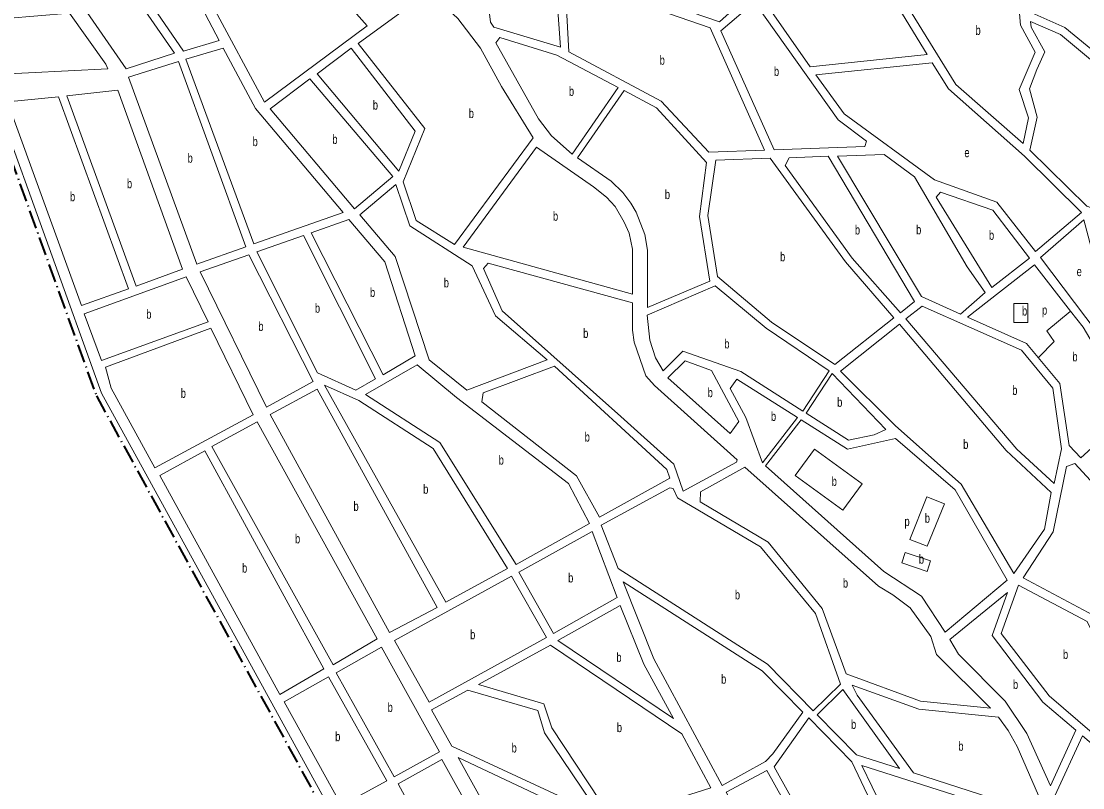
# Model space of a CAD drawing. Extents: x 639657 to 671642, y 222838 to 252123.
# Drawn here: x 652754 to 653901, y 228228 to 229056 of the extents above; entities that cross this region are included whole.
import ezdxf

# ---------------------------------------------------------------- set-up
doc = ezdxf.new("R2010")
doc.units = 0
doc.header["$LTSCALE"] = 4
doc.linetypes.add('DOT_DASHED', pattern=[7.7, 5, -1.2, 0.3, -1.2])
for name, color, linetype, lineweight in [('1', 7, 'Continuous', 13), ('21', 7, 'Continuous', 13), ('4', 7, 'DOT_DASHED', 40)]:
    doc.layers.add(name, color=color, linetype=linetype, lineweight=lineweight)
doc.layers.add('7', color=7, linetype='Continuous')

msp = doc.modelspace()

# ---------------------------------------------------------------- linework, layer by layer
at = {"layer": '1'}
for points in [[(653811.35, 229115.41), (653842.94, 229066.23), (653881.75, 229048.94), (653947.92, 228994.59), (653951.13, 229032.65), (653909.17, 229080.36), (653893.82, 229167.24), (653886.37, 229182.41), (653818.23, 229185.35), (653755.78, 229259.96), (653702.93, 229253.35), (653625.12, 229281.73), (653610.16, 229299.44), (653612.04, 229325.39), (653532.94, 229354.14), (653459.475, 229409.417), (653426.2, 229326.26), (653561.85, 229249.61), (653635.08, 229238.77), (653687.55, 229168.52), (653763.64, 229139.35)], [(652833.34, 229163.27), (652929.38, 229023.56), (652967.93, 229035.13), (652948.95, 229070.5), (652943.35, 229138.98), (652895.2, 229194.68)], [(653387.08, 229096.96), (653508.45, 229055.25), (653540.1, 229083.87), (653435.62, 229176.62), (653392.23, 229190.25)], [(652777.42, 229134.78), (652867.47, 229004.32), (652919.66, 229021.23), (652824.32, 229158.9)], [(653675.24, 229131.17), (653763.75, 228987.51), (653836.5, 228923.62), (653842.49, 228951.64), (653832.4, 228982.03), (653849.8, 229022.23), (653833.96, 229051.69), (653832.73, 229064), (653806.07, 229108.19), (653759.6, 229131.24), (653689.3, 229158.52)], [(653260.52, 229131.76), (653258.29, 229078.93), (653261.1, 229054.91), (653264.61, 229049.33), (653336.54, 229027.63), (653330.99, 229107.86)], [(653341.47, 229103.1), (653345.53, 229022.76), (653445.35, 228969.54), (653497.06, 228914.56), (653557.04, 228916.62), (653498.36, 229048.66)], [(653194.73, 229087.85), (653225.83, 229058.89), (653250.17, 229026.77), (653272.93, 228985.4), (653307.12, 228929.98), (653222.29, 228814.7), (653180.59, 228840.74), (653166.78, 228882.3), (653189.98, 228939.93), (653117.98, 229031.93)], [(653510.09, 229045.26), (653567.52, 228916.98), (653665.49, 228920.35), (653667.35, 228926.26), (653636.64, 228949.17), (653546.22, 229076.33)], [(652543.05, 229031.04), (652552.08, 228972.93), (652718.57, 228997.74), (652847.65, 229004.49), (652845.44, 229009.49), (652806.27, 229064.53), (652737.52, 229058.81)], [(653843.89, 228916.6), (653905.35, 228856.27), (653975.95, 228830.48), (653996.82, 228842.26), (653939.76, 228989.19), (653877.04, 229041.4), (653844.69, 229055.43), (653845.41, 229049.52), (653860.01, 229022.64), (653851.36, 229003.59), (653843.68, 228982.87), (653851.89, 228952.15)], [(653266.98, 229032.3), (653312.76, 228950.32), (653326.89, 228932.14), (653349.21, 228912.27), (653398.97, 228984.28), (653332.75, 229019.28), (653271.26, 229038.12)], [(652931.97, 229014.97), (653005.47, 228815.27), (653102, 228849.35), (653007.18, 228961.39), (652972.08, 229026.65)], [(653110.57, 229026.7), (653073.61, 228999.02), (653161.87, 228894.05), (653179.56, 228937.12)], [(652870.01, 228995.46), (652943.68, 228793.55), (652996.77, 228812.13), (652923.94, 229012.45)], [(653612.79, 228998.06), (653643.23, 228955.7), (653740.85, 228884.57), (653808.05, 228860.48), (653849.87, 228806.97), (653899.67, 228849.27), (653838.05, 228909.92), (653755.97, 228982.87), (653738.36, 229010.98)], [(653065.94, 228993.42), (653022.81, 228961.1), (653114.13, 228853.3), (653155.38, 228888.19)], [(652738.93, 228968.88), (652794.2, 228974.09), (652869.76, 228766.76), (652819.08, 228748.78)], [(652803.33, 228975.29), (652858.44, 228981.2), (652928.38, 228788.2), (652878.13, 228769.68)], [(653354.92, 228908.42), (653391.38, 228883), (653403.94, 228871), (653412.79, 228859.36), (653418.52, 228849.55), (653428, 228825.39), (653430.85, 228808.57), (653430.56, 228746.6), (653497.92, 228775.24), (653487.06, 228844.76), (653494.52, 228903.21), (653440.32, 228962.32), (653405.48, 228980.92)], [(653231.49, 228811.93), (653414.5, 228761.06), (653414.45, 228809.71), (653410.8, 228826.89), (653405.66, 228838.81), (653395.87, 228855.71), (653386.33, 228865.78), (653372.32, 228876.92), (653310.65, 228919.67)], [(653504.72, 228905.87), (653496.09, 228845.92), (653506.4, 228780.16), (653564.87, 228730.84), (653633, 228685.1), (653697.07, 228735.66), (653644.64, 228795.91), (653563.14, 228908.04)], [(653583.94, 228908.32), (653579.66, 228899.87), (653651.83, 228799.96), (653703.94, 228740.95), (653719.22, 228753.3), (653625.96, 228910.06)], [(653635.96, 228910.26), (653726.73, 228758.43), (653768.82, 228739.64), (653795.56, 228762.79), (653776.07, 228790.51), (653719.23, 228887.83), (653686.53, 228911.81)], [(653173.87, 228834.68), (653241.39, 228791.65), (653266.39, 228737.49), (653322.16, 228690.26), (653235.3, 228657.47), (653194.91, 228690.31), (653157.91, 228801.86), (653119.84, 228846.81), (653158.67, 228879.38)], [(653747.5, 228871.37), (653742.68, 228865.66), (653802.86, 228768.18), (653843.66, 228799.86), (653803.99, 228851.76)], [(653067.17, 228827.36), (653144.99, 228674.08), (653179.76, 228694.57), (653147.01, 228795.82), (653107.92, 228841.84)], [(653855.36, 228800.75), (653916.47, 228719.62), (653929.74, 228737.89), (653902.28, 228841.48)], [(653008.71, 228806.68), (653074.23, 228676.26), (653115.47, 228657.54), (653136.89, 228669.5), (653058.85, 228824.45)], [(652947.4, 228785.23), (653019.03, 228638.92), (653069.36, 228666.74), (652999.8, 228803.65)], [(652821.89, 228739.97), (652840.57, 228689.4), (652955.83, 228731.26), (652932.05, 228779.61)], [(653430.48, 228738.32), (653433.25, 228711.51), (653439.43, 228692.13), (653447.49, 228678.34), (653468.81, 228699.58), (653531.66, 228677.47), (653598.44, 228634.79), (653627.11, 228678.36), (653559.03, 228724.21), (653503.74, 228770.16)], [(653709.76, 228734.46), (653829.79, 228593.75), (653870.32, 228556.46), (653878.21, 228593.9), (653868.82, 228659.6), (653834.99, 228700.45), (653727.56, 228748.12)], [(652844.86, 228682.25), (652851.16, 228659.55), (652898.38, 228573.69), (653004.64, 228630.84), (652958.85, 228724.44)], [(653826.76, 228459.32), (653769.76, 228555.94), (653698.73, 228618.87), (653639.42, 228677.92), (653702.9, 228728.64), (653818.4, 228592.21), (653866.88, 228546.78), (653859.65, 228507.35)], [(653206.2, 228600.89), (653288.85, 228469.23), (653368.14, 228513.3), (653345.26, 228556.5), (653224.2, 228649.59), (653181.78, 228684.78), (653126.01, 228652.88)], [(653452.72, 228670.62), (653520.15, 228610.68), (653529.41, 228623.67), (653500, 228678.67), (653471.26, 228689)], [(653251.73, 228644.68), (653354.05, 228564.86), (653378.8, 228520.38), (653454.73, 228562.27), (653451.69, 228571.88), (653330.19, 228683.35), (653253.21, 228654.41)], [(653602.21, 228632.6), (653648.04, 228603.5), (653675.54, 228609.18), (653688.31, 228614.81), (653630.13, 228675.41)], [(653199, 228594.31), (653279.57, 228464.93), (653212.69, 228428.3), (653081.78, 228662.79), (653118.72, 228646.37)], [(653527.38, 228669.34), (653520, 228659.32), (653536.92, 228627.99), (653554.97, 228578.97), (653592.82, 228627.95)], [(653151.82, 228395.79), (653023.02, 228631.03), (653073.89, 228658.37), (653203.41, 228422.7)], [(653091.08, 228360.66), (652960.07, 228596.53), (653008.96, 228623.32), (653138.44, 228388.88)], [(653558.391, 228575.659), (653596.75, 228625.43), (653646.88, 228593.77), (653698.66, 228605.16), (653763.28, 228549.74), (653819.52, 228452.22), (653752.33, 228395.93), (653726.89, 228435.09), (653686.09, 228461.48)], [(652903.55, 228565.09), (652952.29, 228592), (653080.84, 228356.36), (653033.35, 228328.69)], [(653561.02, 228493.41), (653487.65, 228536.84), (653487.93, 228547.54), (653536.06, 228574.24), (653680.27, 228445.68), (653695.68, 228436.48), (653714.42, 228422.48), (653736.72, 228391.25), (653743.08, 228372), (653801.52, 228314.11), (653725.6, 228321.5), (653645.58, 228351), (653619.42, 228421.47)], [(653883.4, 228574.99), (653892.51, 228578.03), (653989.83, 228472.58), (654010.14, 228473.42), (654027.16, 228494.01), (654071.54, 228420.2), (653955.49, 228346.83), (653940.12, 228357.61), (653912.25, 228414.53), (653836.58, 228454.74), (653868.93, 228504.55)], [(653380.72, 228511.6), (653454.87, 228551.84), (653458.36, 228551.37), (653463.02, 228541.06), (653552.74, 228488.27), (653612.24, 228416.07), (653639.23, 228339.97), (653609.75, 228311.07), (653560.25, 228361.36), (653398.9, 228464.66)], [(653370.93, 228504.69), (653291.83, 228460.71), (653329.25, 228394.79), (653398.11, 228433.35)], [(653157.25, 228387.01), (653194.85, 228320.51), (653321.48, 228390.25), (653283.74, 228456.38)], [(653404.44, 228450.34), (653437.73, 228367.28), (653511.56, 228230.51), (653558.29, 228256.25), (653566.32, 228264.61), (653598.58, 228309.84), (653554.59, 228354.25)], [(653831.73, 228446.72), (653812.92, 228394.44), (653864.68, 228327.14), (653911.23, 228287.41), (653948.52, 228339.54), (653933.49, 228350.49), (653905.67, 228407.69)], [(653819.62, 228439.04), (653757.25, 228388.11), (653766.82, 228372.14), (653817.17, 228321.64), (653840.72, 228286.55), (653866.34, 228230.26), (653893.6, 228290.35), (653857.99, 228320.34), (653803.31, 228392.47)], [(653401.31, 228424.87), (653333.9, 228387.08), (653458.92, 228302.92), (653426.8, 228361.55)], [(653205.89, 228266.88), (653143.13, 228379.86), (653094.22, 228352.06), (653156.81, 228239.91)], [(653325.91, 228382.16), (653247.99, 228339.7), (653318.74, 228318.65), (653327.17, 228292.58), (653392.42, 228194.12), (653499.27, 228227.94), (653467.85, 228286.25)], [(653085.89, 228347.95), (653037.9, 228320.81), (653099.99, 228208.73), (653149.09, 228235.57)], [(653197.16, 228312.27), (653219.24, 228273), (653379.03, 228198.8), (653319.46, 228287.24), (653312.06, 228311.32), (653236.68, 228333.43)], [(653641.67, 228334.17), (653613.95, 228306.89), (653656.44, 228263.56), (653703, 228248.91)], [(653651.85, 228338.72), (653657.26, 228328.17), (653718.27, 228244.19), (653863.13, 228197.32), (653830.19, 228272.71), (653820.3, 228289.85), (653809.93, 228304.42), (653723.76, 228312.79)], [(653567.5, 228250.7), (653645.21, 228111.53), (653713.86, 228148.9), (653688.56, 228177.86), (653651.58, 228255.91), (653604.89, 228303.37)], [(653999.51, 228200.07), (653900.72, 228283.99), (653871.05, 228219.16), (653882.26, 228194.82), (653900.61, 228186.51), (653911.58, 228169.53), (653962.19, 228138.29), (654049.93, 228120.63), (654055.79, 228128.91)], [(653226.16, 228260.62), (653292.25, 228141.38), (653378.96, 228188.7)], [(653208.5, 228258.42), (653161.31, 228232.13), (653229.35, 228106.69), (653278.05, 228133.53)], [(653662.5, 228252.19), (653695.74, 228182.83), (653742.82, 228130.11), (653893.21, 228126.66), (653867.9, 228186.65)], [(653515.72, 228223.11), (653593.54, 228082.92), (653637.44, 228107.31), (653559.51, 228246.59)]]:
    msp.add_lwpolyline(points, close=True, dxfattribs=at)
for points in [[(653549.53, 229088.24), (653606.47, 229006.54), (653732.9, 229019.83), (653667.88, 229126.8), (653605.07, 229151.28), (653556.41, 229241.94), (653537.956, 229252.419)], [(652960.607, 229076.586), (652961.09, 229072.02), (653016.89, 228968.23), (653127.83, 229050.75), (653090.71, 229092.8), (653067.566, 229120.908)], [(652721.144, 228967.066), (652727.37, 228968.04), (652840.64, 228654.32), (653505.16, 227445.52), (653736.61, 227336.66), (653997.8, 227222.88), (654191.766, 227095.851), (654189.938, 227093.586), (654189.534, 227093.086)], [(653438.24, 228662.51), (653429.07, 228672.86), (653416.16, 228709.15), (653414.51, 228722.15), (653414.42, 228751.66), (653258.36, 228794.71), (653253.38, 228788.89)], [(653253.38, 228788.89), (653273.73, 228743.21), (653402.01, 228629.13)], [(653887.861, 228742.805), (653848.79, 228792.57), (653776.51, 228736.28)], [(653852.938, 228692.656), (653876.44, 228664.46), (653886.43, 228597.52), (653898.88, 228584.45), (653933.51, 228615.57), (653957.16, 228631.28), (653901.62, 228725.28), (653887.861, 228742.805)], [(653776.51, 228736.28), (653840.24, 228707.89), (653852.938, 228692.656)], [(653469.17, 228548.28), (653527.02, 228579.53), (653527.55, 228582), (653438.24, 228662.51)], [(653402.01, 228629.13), (653459.3, 228577.49), (653469.17, 228548.28)]]:
    msp.add_lwpolyline(points, dxfattribs=at)
at = {"layer": '21'}
for points in [[(653826.477, 228750.809), (653841.855, 228750.809), (653841.855, 228730.293), (653826.477, 228730.293)], [(653611.183, 228593.732), (653662.716, 228556.297), (653641.939, 228527.696), (653590.406, 228565.131)], [(653714.344, 228496.281), (653733.107, 228488.772), (653751.508, 228534.749), (653732.745, 228542.258)], [(653709.218, 228482.176), (653736.71, 228473.006), (653732.926, 228461.66), (653705.434, 228470.83)]]:
    msp.add_lwpolyline(points, close=True, dxfattribs=at)
msp.add_lwpolyline([(653852.938, 228692.656), (653853.438, 228693.156), (653870.048, 228709.777), (653862.359, 228721.317), (653887.361, 228742.384), (653887.861, 228742.805)], dxfattribs=at)
at = {"layer": '4'}
msp.add_lwpolyline([(652721.144, 228967.066), (652835.14, 228651.18), (653499.57, 227439.02), (653726.56, 227332.83), (653996.15, 227217.92), (654189.534, 227093.086), (654206.939, 227081.85), (654311.793, 227014.164), (654317.98, 227010.17)], dxfattribs=at)

# ---------------------------------------------------------------- texts
at = {"layer": '7', "width": 0.75}
for s, p in [('b', (653785.211, 229041.07)), ('b', (653443.859, 229008.83)), ('b', (653567.362, 228996.655)), ('b', (653345.781, 228975.195)), ('b', (653133.877, 228960.375)), ('b', (653237.542, 228951.275)), ('b', (653003.983, 228920.96)), ('b', (653090.134, 228923.36)), ('e', (653773.183, 228908.975)), ('b', (652933.739, 228903)), ('b', (652868.21, 228875.44)), ('b', (652806.656, 228861.435)), ('b', (653449.465, 228863.76)), ('b', (653328.571, 228840.365)), ('b', (653654.821, 228825.505)), ('b', (653721, 228825.725)), ('b', (653799.723, 228819.775)), ('b', (653573.994, 228796.57)), ('e', (653894.503, 228780.55)), ('b', (653210.555, 228768.425)), ('b', (653130.83, 228757.96)), ('b', (652889.071, 228734.505)), ('b', (653071.295, 228740.995)), ('b', (653835.448, 228737.987)), ('p', (653857.089, 228738.921)), ('b', (653010.177, 228721.285)), ('b', (653361.181, 228713.82)), ('b', (653513.717, 228702.475)), ('b', (653889.87, 228688.51)), ('b', (653824.859, 228652.29)), ('b', (652926.325, 228649.065)), ('b', (653495.756, 228649.84)), ('b', (653635.665, 228639.455)), ('b', (653564.11, 228624.155)), ('b', (653362.81, 228601.865)), ('b', (653771.863, 228593.98)), ('b', (653269.894, 228577.005)), ('b', (653629.765, 228553.982)), ('b', (653188.301, 228545.545)), ('b', (653112.99, 228527.08)), ('b', (653730.363, 228514.232)), ('p', (653708.435, 228510.68)), ('b', (653049.814, 228491.99)), ('b', (653723.955, 228469.995)), ('b', (652992.587, 228460.345)), ('b', (653344.961, 228449.74)), ('b', (653641.89, 228444.175)), ('b', (653525.163, 228431.455)), ('b', (653239.035, 228388.445)), ('b', (653879.701, 228367.065)), ('b', (653397.099, 228363.895)), ('b', (653510.255, 228340.425)), ('b', (653825.67, 228334.65)), ('b', (653149.879, 228309.885)), ('b', (653397.583, 228288.14)), ('b', (653650.669, 228291.54)), ('b', (653093.232, 228278.34)), ('b', (653283.878, 228266.115)), ('b', (653766.599, 228268.02))]:
    msp.add_text(s, height=10, dxfattribs=at).set_placement(p)

doc.saveas('drawing.dxf')
